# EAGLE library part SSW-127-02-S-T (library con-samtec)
THROUGH-HOLE .025" SQ POST SOCKET Source: Samtec SSW.pdf
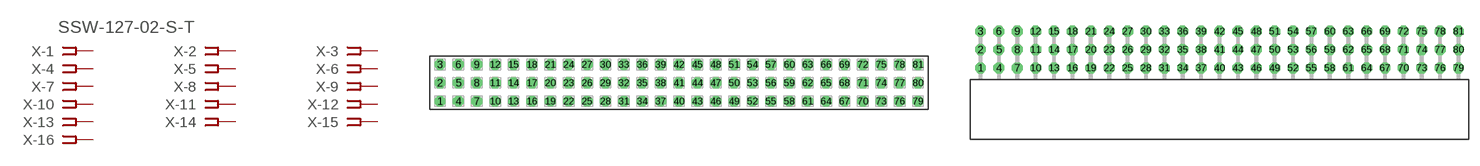
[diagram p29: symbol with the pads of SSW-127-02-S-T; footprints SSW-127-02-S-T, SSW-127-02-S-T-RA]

Designator prefix X; gates -1=FPINV -2=FPIN -3=FPIN -4=FPIN -5=FPIN -6=FPIN -7=FPIN -8=FPIN -9=FPIN -10=FPIN -11=FPIN -12=FPIN -13=FPIN -14=FPIN -15=FPIN -16=FPIN -17=FPIN -18=FPIN -19=FPIN -20=FPIN -21=FPIN -22=FPIN -23=FPIN -24=FPIN -25=FPIN -26=FPIN -27=FPIN -28=FPIN -29=FPIN -30=FPIN -31=FPIN -32=FPIN -33=FPIN -34=FPIN -35=FPIN -36=FPIN -37=FPIN -38=FPIN -39=FPIN -40=FPIN -41=FPIN -42=FPIN -43=FPIN -44=FPIN -45=FPIN -46=FPIN -47=FPIN -48=FPIN -49=FPIN -50=FPIN -51=FPIN -52=FPIN -53=FPIN -54=FPIN -55=FPIN -56=FPIN -57=FPIN -58=FPIN -59=FPIN -60=FPIN -61=FPIN -62=FPIN -63=FPIN -64=FPIN -65=FPIN -66=FPIN -67=FPIN -68=FPIN -69=FPIN -70=FPIN -71=FPIN -72=FPIN -73=FPIN -74=FPIN -75=FPIN -76=FPIN -77=FPIN -78=FPIN -79=FPIN -80=FPIN -81=FPIN

## SSW-127-02-S-T (MPN: SSW-127-02-S-T; OC_FARNELL: unknown; OC_NEWARK: 82P9695)  [SSW-127-02-S-T]
1  -1:1  pas
2  -2:1  pas
3  -3:1  pas
4  -4:1  pas
5  -5:1  pas
6  -6:1  pas
7  -7:1  pas
8  -8:1  pas
9  -9:1  pas
10  -10:1  pas
11  -11:1  pas
12  -12:1  pas
13  -13:1  pas
14  -14:1  pas
15  -15:1  pas
16  -16:1  pas
17  -17:1  pas
18  -18:1  pas
19  -19:1  pas
20  -20:1  pas
21  -21:1  pas
22  -22:1  pas
23  -23:1  pas
24  -24:1  pas
25  -25:1  pas
26  -26:1  pas
27  -27:1  pas
28  -28:1  pas
29  -29:1  pas
30  -30:1  pas
31  -31:1  pas
32  -32:1  pas
33  -33:1  pas
34  -34:1  pas
35  -35:1  pas
36  -36:1  pas
37  -37:1  pas
38  -38:1  pas
39  -39:1  pas
40  -40:1  pas
41  -41:1  pas
42  -42:1  pas
43  -43:1  pas
44  -44:1  pas
45  -45:1  pas
46  -46:1  pas
47  -47:1  pas
48  -48:1  pas
49  -49:1  pas
50  -50:1  pas
51  -51:1  pas
52  -52:1  pas
53  -53:1  pas
54  -54:1  pas
55  -55:1  pas
56  -56:1  pas
57  -57:1  pas
58  -58:1  pas
59  -59:1  pas
60  -60:1  pas
61  -61:1  pas
62  -62:1  pas
63  -63:1  pas
64  -64:1  pas
65  -65:1  pas
66  -66:1  pas
67  -67:1  pas
68  -68:1  pas
69  -69:1  pas
70  -70:1  pas
71  -71:1  pas
72  -72:1  pas
73  -73:1  pas
74  -74:1  pas
75  -75:1  pas
76  -76:1  pas
77  -77:1  pas
78  -78:1  pas
79  -79:1  pas
80  -80:1  pas
81  -81:1  pas

## SSW-127-02-S-TRA (MPN: SSW-127-02-S-T-RA; OC_FARNELL: unknown; OC_NEWARK: 82P9696)  [SSW-127-02-S-T-RA]
Pads as for SSW-127-02-S-T

## Footprint SSW-127-02-S-T (pad centres in mm)
THROUGH-HOLE .025" SQ POST SOCKET Source: Samtec SSW.pdf
drill 1 pad 1.5 octagon: 1 -33.02,-2.54; 2 -33.02,0; 3 -33.02,2.54; 4 -30.48,-2.54; 5 -30.48,0; 6 -30.48,2.54; 7 -27.94,-2.54; 8 -27.94,0; 9 -27.94,2.54; 10 -25.4,-2.54; 11 -25.4,0; 12 -25.4,2.54; 13 -22.86,-2.54; 14 -22.86,0; 15 -22.86,2.54; 16 -20.32,-2.54; 17 -20.32,0; 18 -20.32,2.54; 19 -17.78,-2.54; 20 -17.78,0; 21 -17.78,2.54; 22 -15.24,-2.54; 23 -15.24,0; 24 -15.24,2.54; 25 -12.7,-2.54; 26 -12.7,0; 27 -12.7,2.54; 28 -10.16,-2.54; 29 -10.16,0; 30 -10.16,2.54; 31 -7.62,-2.54; 32 -7.62,0; 33 -7.62,2.54; 34 -5.08,-2.54; 35 -5.08,0; 36 -5.08,2.54; 37 -2.54,-2.54; 38 -2.54,0; 39 -2.54,2.54; 40 0,-2.54; 41 0,0; 42 0,2.54; 43 2.54,-2.54; 44 2.54,0; 45 2.54,2.54; 46 5.08,-2.54; 47 5.08,0; 48 5.08,2.54; 49 7.62,-2.54; 50 7.62,0; 51 7.62,2.54; 52 10.16,-2.54; 53 10.16,0; 54 10.16,2.54; 55 12.7,-2.54; 56 12.7,0; 57 12.7,2.54; 58 15.24,-2.54; 59 15.24,0; 60 15.24,2.54; 61 17.78,-2.54; 62 17.78,0; 63 17.78,2.54; 64 20.32,-2.54; 65 20.32,0; 66 20.32,2.54; 67 22.86,-2.54; 68 22.86,0; 69 22.86,2.54; 70 25.4,-2.54; 71 25.4,0; 72 25.4,2.54; 73 27.94,-2.54; 74 27.94,0; 75 27.94,2.54; 76 30.48,-2.54; 77 30.48,0; 78 30.48,2.54; 79 33.02,-2.54; 80 33.02,0; 81 33.02,2.54

## Footprint SSW-127-02-S-T-RA (pad centres in mm)
THROUGH-HOLE .025" SQ POST SOCKET Source: Samtec SSW.pdf
drill 1 pad 1.5 octagon: 1 -33.02,1.524; 2 -33.02,4.064; 3 -33.02,6.604; 4 -30.48,1.524; 5 -30.48,4.064; 6 -30.48,6.604; 7 -27.94,1.524; 8 -27.94,4.064; 9 -27.94,6.604; 10 -25.4,1.524; 11 -25.4,4.064; 12 -25.4,6.604; 13 -22.86,1.524; 14 -22.86,4.064; 15 -22.86,6.604; 16 -20.32,1.524; 17 -20.32,4.064; 18 -20.32,6.604; 19 -17.78,1.524; 20 -17.78,4.064; 21 -17.78,6.604; 22 -15.24,1.524; 23 -15.24,4.064; 24 -15.24,6.604; 25 -12.7,1.524; 26 -12.7,4.064; 27 -12.7,6.604; 28 -10.16,1.524; 29 -10.16,4.064; 30 -10.16,6.604; 31 -7.62,1.524; 32 -7.62,4.064; 33 -7.62,6.604; 34 -5.08,1.524; 35 -5.08,4.064; 36 -5.08,6.604; 37 -2.54,1.524; 38 -2.54,4.064; 39 -2.54,6.604; 40 0,1.524; 41 0,4.064; 42 0,6.604; 43 2.54,1.524; 44 2.54,4.064; 45 2.54,6.604; 46 5.08,1.524; 47 5.08,4.064; 48 5.08,6.604; 49 7.62,1.524; 50 7.62,4.064; 51 7.62,6.604; 52 10.16,1.524; 53 10.16,4.064; 54 10.16,6.604; 55 12.7,1.524; 56 12.7,4.064; 57 12.7,6.604; 58 15.24,1.524; 59 15.24,4.064; 60 15.24,6.604; 61 17.78,1.524; 62 17.78,4.064; 63 17.78,6.604; 64 20.32,1.524; 65 20.32,4.064; 66 20.32,6.604; 67 22.86,1.524; 68 22.86,4.064; 69 22.86,6.604; 70 25.4,1.524; 71 25.4,4.064; 72 25.4,6.604; 73 27.94,1.524; 74 27.94,4.064; 75 27.94,6.604; 76 30.48,1.524; 77 30.48,4.064; 78 30.48,6.604; 79 33.02,1.524; 80 33.02,4.064; 81 33.02,6.604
